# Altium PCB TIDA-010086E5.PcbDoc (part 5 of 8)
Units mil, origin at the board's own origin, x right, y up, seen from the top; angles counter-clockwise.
Board outline 6400 x 6200 mil, 6 copper layers (Top Layer, Power, AGND, Signal, PGND, Bottom Layer), stack 70.536 mil thick; 717 components, 376 nets, 2259 pads, 2183 vias.
Unrouted connection lines stored in the file: 1424.
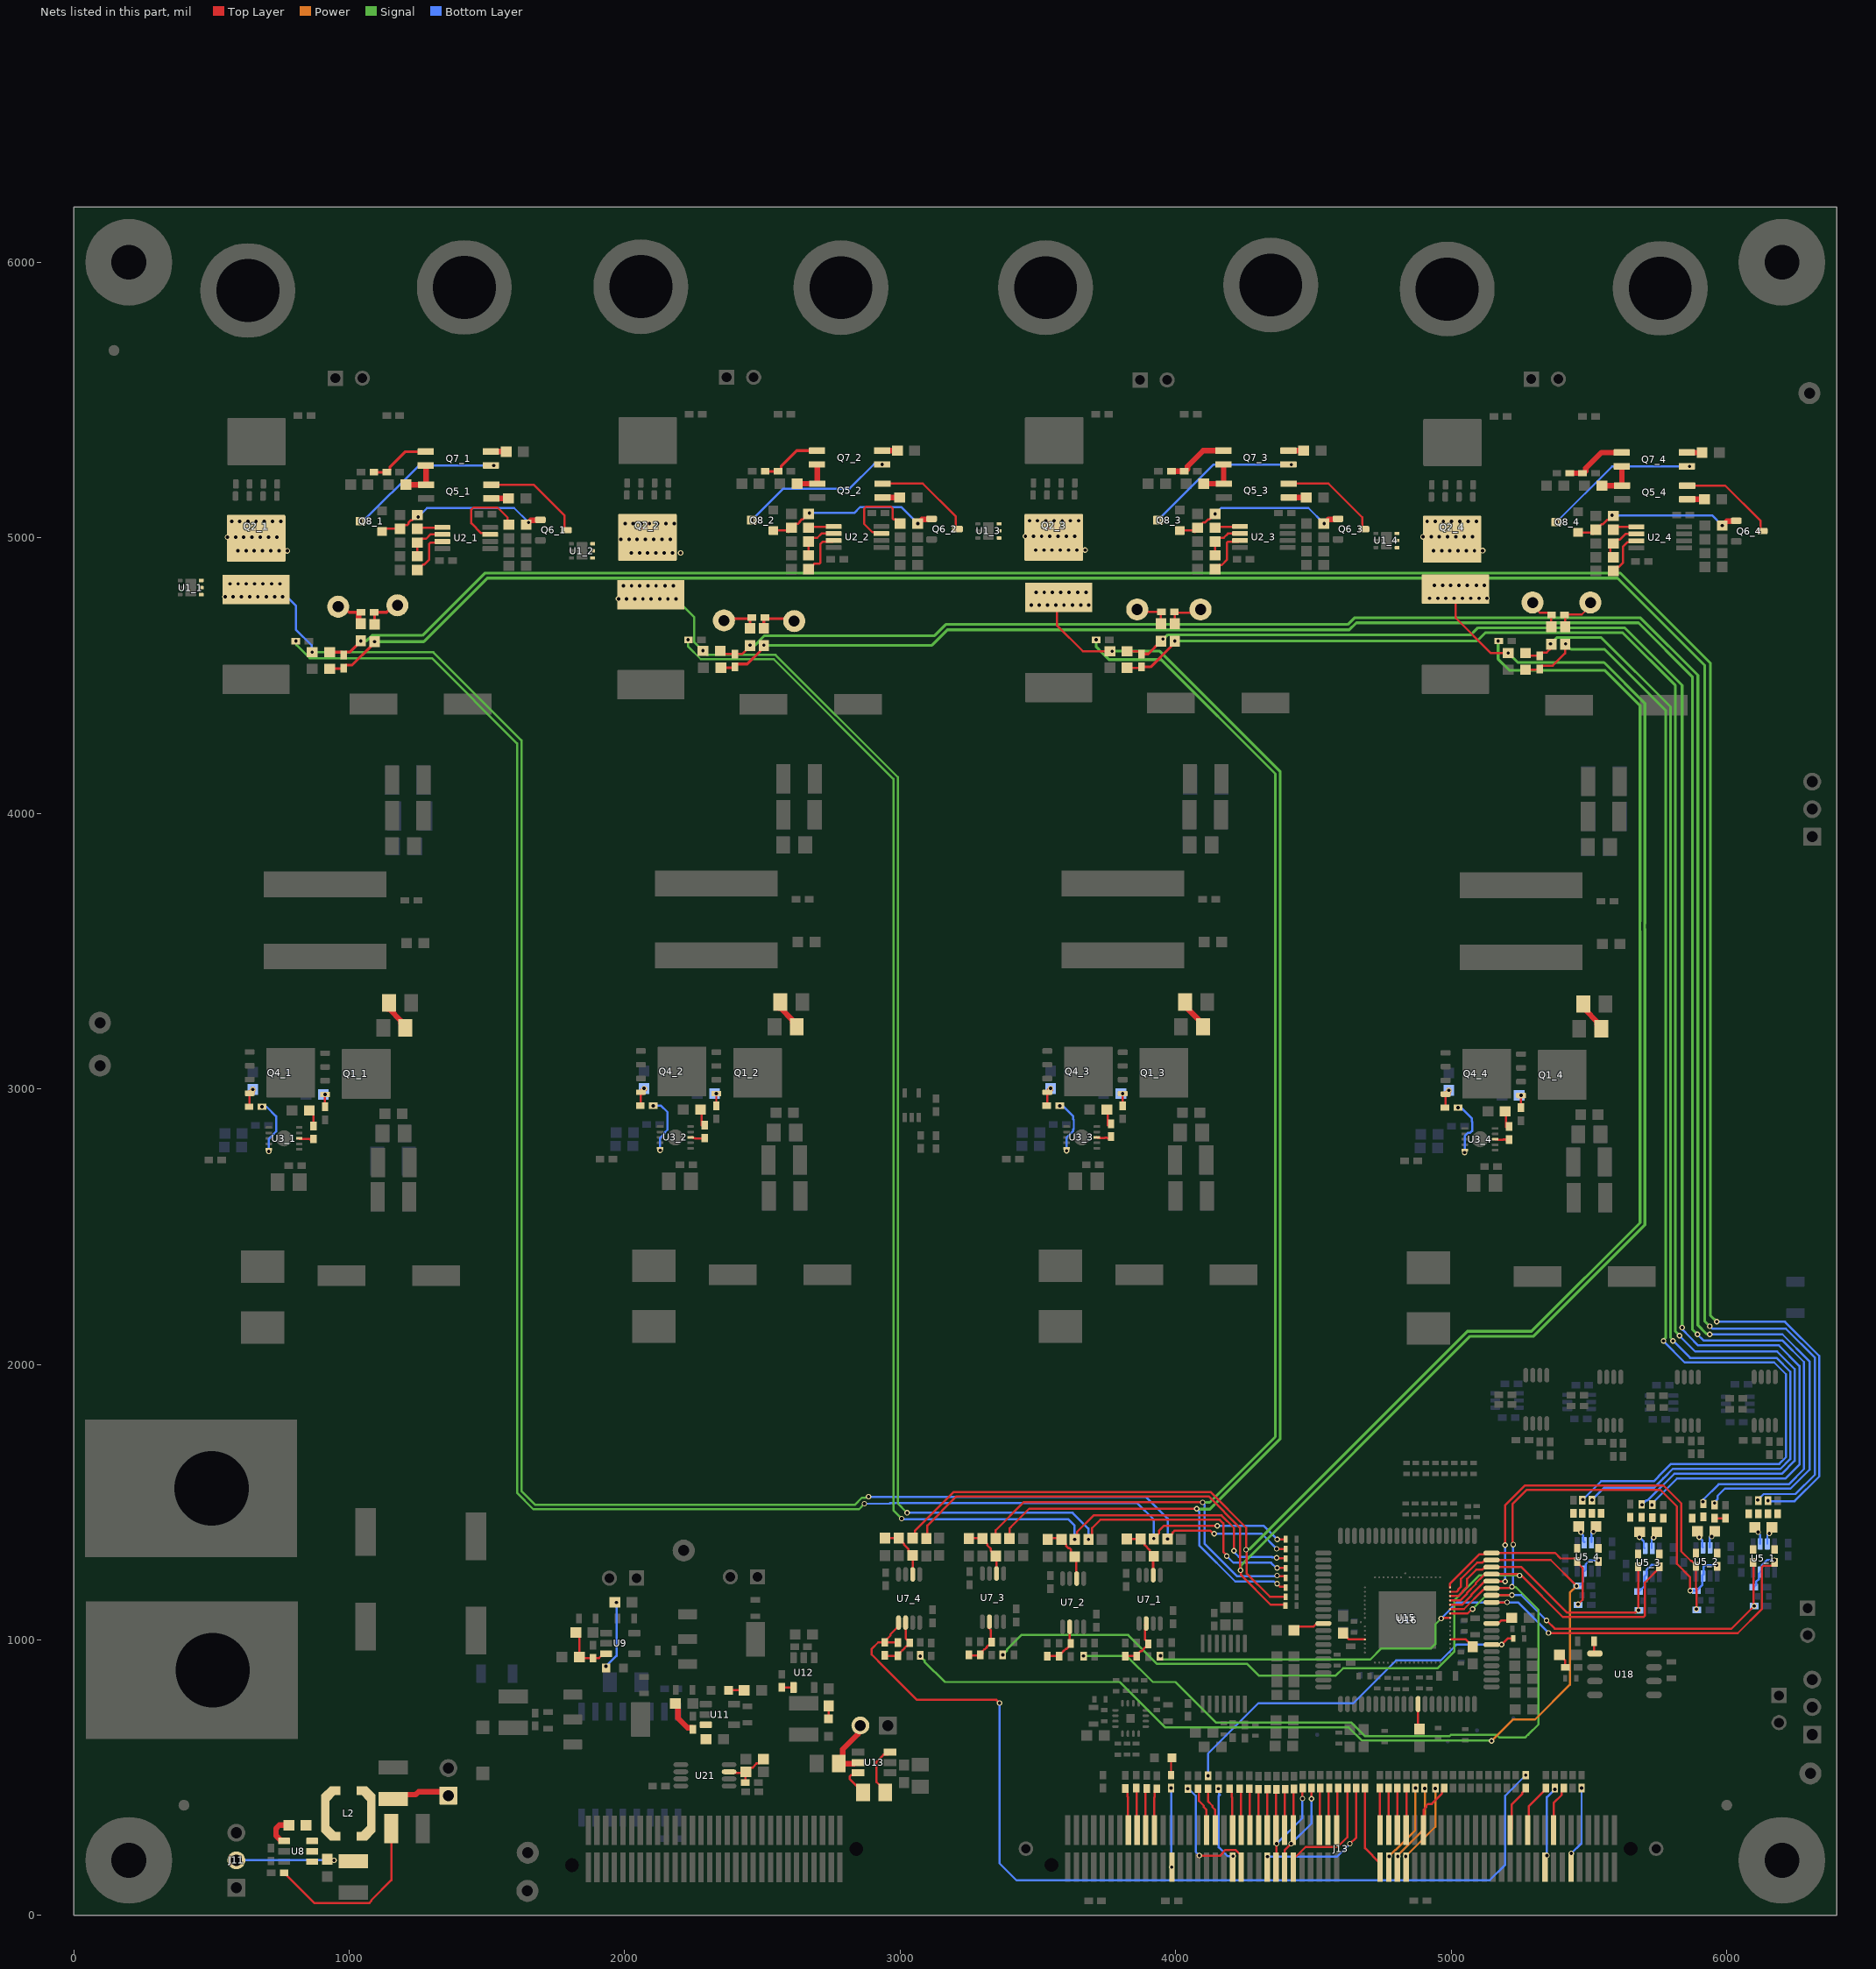
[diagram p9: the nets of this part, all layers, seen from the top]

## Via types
v1: diameter 20, hole 12.5, Top Layer to Bottom Layer, 1408 vias
v2: diameter 20, hole 12, Top Layer to Bottom Layer, tented both sides, 775 vias

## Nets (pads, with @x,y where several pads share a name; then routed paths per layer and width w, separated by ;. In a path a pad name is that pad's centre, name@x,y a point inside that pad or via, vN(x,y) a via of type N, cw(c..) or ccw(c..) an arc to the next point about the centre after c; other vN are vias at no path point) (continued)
IOCP4: C35_4.1 R51_4.1 R128.2 U7_4.1 | length 3579.4
  Top Layer w7.87: C35_4.1@2991.87,990 2991.59,990.28 2944.09,990.28 R51_4.1@2943.3,991.08 ; U7_4.1@2993.8,1062.71 2993.8,1047.09 2990.24,1043.52 2987.83,1043.52 2964.36,1020.05 2964.36,1016.08 2943.3,995.02 R51_4.1@2943.3,991.08 ; v2(3360.22,770.9) 3348.89,782.22 3060.64,782.22 2941.69,901.18 2896.33,946.54 2896.33,967.36 2920.05,991.08 R51_4.1@2943.3,991.08 ; R128.2@5270.07,509.13 v2(5270.3,509.13)
  Bottom Layer w7.87: v2(3360.22,770.9) 3360.22,189.51 3422.09,127.63 5139.36,127.63 5195.73,184.01 5195.73,434.56 v2(5270.3,509.13)
IoutN1: R40_1.2 R41_1.2 U15.58 U16.74 | length 1447.1
  Top Layer w7.87: U15.58@4995.57,1095.97 5059.06,1095.97 5074.92,1111.83 v2(5077.45,1111.83) ; U16.74@5146.16,1161.92 5146.5,1162.26 5219.52,1162.26 v2(5219.86,1162.6) ; v2(5345.75,1070.57) 5375.76,1040.56 5540.05,1040.56 5540.38,1040.23 6016.3,1040.23 v2(6099.19,1123.12) 6097.62,1124.7 6097.62,1279.31 R41_1.2@6096.04,1280.88
  Signal w7.87: v2(5077.45,1111.83) 5128.23,1162.6 v2(5219.86,1162.6)
  Bottom Layer w7.87: v2@5222.39,1163.33 5223.11,1162.6 5253.72,1162.6 v2(5345.75,1070.57)
IoutN2: R40_2.2 R41_2.2 U15.60 U16.76 | length 1618.9
  Top Layer w7.87: U15.60@4995.57,1127.47 5036.22,1127.47 5038.73,1127.47 5073.33,1162.06 5073.33,1164.58 5116.93,1208.18 5117.91,1208.18 5122.83,1213.1 U16.76@5146.16,1213.1 5146.65,1212.61 5195.32,1212.61 v2(5195.81,1212.12) ; v2(5195.81,1343.78) 5195.81,1489.03 5267.53,1560.75 5769.47,1560.75 5834.9,1495.32 5834.9,1321.5 5869.65,1286.76 5872.27,1286.76 5889.74,1269.28 R41_2.2@5889.74,1267.07 ; R41_2.2@5888.02,1267.07 5888.02,1188.5 5889.74,1186.77 v2(5889.74,1111.83)
  Bottom Layer w7.87: v2(5195.81,1212.12) v2(5195.81,1343.78)
IoutN3: R40_3.2 R41_3.2 U15.62 U16.78 | length 952.6
  Top Layer w7.87: U15.62@4995.57,1158.97 5025.69,1158.97 5041.83,1175.11 5041.83,1177.62 5057.58,1193.37 5057.58,1221.53 5090.48,1254.44 5112.01,1254.44 5116.93,1259.36 5117.91,1259.36 5122.83,1264.28 U16.78@5146.16,1264.28 ; U16.78@5169.07,1264.96 5169.75,1264.28 5255.08,1264.28 5420.6,1098.76 5668.66,1098.76 5677.57,1107.66 v2(5679.34,1107.66) 5678.72,1108.28 5678.72,1264.16 R41_3.2@5678.1,1264.78
IoutN4: R40_4.2 R41_4.2 U15.64 U16.80 | length 707
  Top Layer w7.87: U15.64@4995.57,1190.46 4995.57,1204.9 5101.85,1311.18 5118.55,1311.18 5122.83,1315.46 5377.21,1315.46 5397.15,1295.53 5450.2,1295.53 5457.01,1288.72 5457.01,1280.84 5476.85,1261 5476.85,1145.99 v2(5460.35,1129.49)
IoutP1: R33_1.2 R36_1.2 R46_1.1 U5_1.7 U15.57 U16.73 | length 2858.4
  Top Layer w7.87: R46_1.1@3942.54,941.29 3943.63,941.29 v2(3944.68,942.34) ; v2(4963.44,1077.79) 4965.77,1080.11 4974.17,1080.11 4974.28,1080.23 U15.57@4995.98,1080.23 ; U16.73@5146.16,1136.33 v2(5202.9,1136.33) ; v2(5353.14,1025.09) 5353.42,1024.81 5533.53,1024.81 5533.85,1024.48 6039.77,1024.48 6126.95,1111.66 6126.95,1263.38 6132.64,1269.07 6164.94,1269.07 6172.82,1276.94 v2(6172.82,1289.52)
  Signal w7.87: v2(3944.68,942.34) 3947,940.02 3947,932.04 3948.74,930.29 3948.74,928.49 4705.68,928.49 4746.68,969.5 4926.51,969.5 4941.9,984.88 4941.9,1056.24 v2(4963.44,1077.79)
  Bottom Layer w7.87: v2(4963.44,1077.79) 5021.98,1136.33 5241.9,1136.33 v2(5353.14,1025.09) ; R36_1.2@6098.01,1191.75 6098.25,1191.75 6106.13,1199.62 6106.13,1210.76 6116.71,1221.34 6116.71,1240.84 6126.56,1250.68 6126.56,1270.18 6147.07,1290.69 6171.64,1290.69 v2(6172.82,1289.52)
IoutP2: R33_2.2 R36_2.2 R46_2.1 U5_2.7 U15.59 U16.75 | length 4047.8
  Top Layer w7.87: U15.59@4995.57,1111.72 5046.06,1111.72 5116.93,1182.59 5117.91,1182.59 5122.83,1187.51 5210.88,1187.51 5216.62,1193.25 v2(5219.86,1193.25) ; v2(5225,1346.08) 5222.81,1348.28 5222.81,1493.76 5274.05,1545 5758.26,1545 5819.16,1484.1 5819.16,1275.56 5867.02,1227.7 v2(5867.02,1178.65)
  Signal w7.87: v2(3664.6,941.38) v2(3664.6,941.38) 3822.8,941.42 3917.08,847.14 3999.3,847.14 4145.69,700.75 4636.22,700.75 4686.97,649.99 4993.49,649.99 4998.84,655.34 5165.29,655.34 5174.86,645.78 5267.6,645.78 5278.06,656.23 5279.33,656.23 5316.81,693.71 5316.81,1108.57 5233.55,1191.83 5221.28,1191.83 v2(5219.86,1193.25)
  Bottom Layer w7.87: v2(5219.86,1193.25) 5222.18,1195.57 5222.18,1202.42 5223.69,1203.92 5223.69,1344.77 v2(5225,1346.08) ; v2(5867.02,1178.65) 5867.37,1178.29 5889.63,1178.29 R36_2.2@5889.98,1177.94 ; R36_2.2@5888.56,1180.45 5892.5,1180.45 5910.84,1198.8 5910.84,1233.13 5916.04,1238.32 5916.04,1266.52 5920.65,1271.14 v2(5963.36,1271.14)
IoutP3: R33_3.2 R36_3.2 R46_3.1 U5_3.7 U15.61 U16.77 | length 3395.8
  Top Layer w7.87: U15.61@4995.57,1143.22 5032.21,1143.22 5057.58,1168.59 5057.58,1171.1 5089.07,1202.59 5089.07,1205.91 5116.93,1233.77 5117.91,1233.77 5122.83,1238.69 5239.57,1238.69 5244.49,1233.77 v2(5247.77,1233.77) 5250.09,1231.45 5256.98,1231.45 5405.42,1083.01 5697.2,1083.01 5703.05,1088.87 5703.05,1209.03 5754.87,1260.85 5752.72,1262.99 v2(5752.72,1272.13)
  Signal w7.87: v2(3372.1,945.74) 3388.19,961.82 3388.19,966.07 3439.74,1017.63 3827.55,1017.63 3932.43,912.75 4259.13,912.75 4301.29,870.59 4580.76,870.59 4606.99,896.81 4950.3,896.81 5011.6,958.12 5011.6,1144.43 5101.1,1233.93 5247.62,1233.93 v2(5247.77,1233.77)
  Bottom Layer w7.87: R36_3.2@5678.16,1176.28 5682.1,1176.28 5700.44,1194.63 5700.44,1228.96 5708.61,1237.13 5708.61,1254.09 5726.66,1272.13 v2(5752.72,1272.13)
IoutP4: R33_4.2 R36_4.2 R46_4.1 U5_4.7 U15.63 U16.79 | length 3647.1
  Top Layer w7.87: U15.63@4995.57,1174.71 5019.16,1174.71 5026.08,1181.63 5026.08,1184.14 5035.35,1193.41 5035.35,1221.58 5093.8,1280.03 5112.01,1280.03 5116.93,1284.95 5117.91,1284.95 5122.83,1289.87 5360.82,1289.87 v2(5455.04,1195.65)
  Signal w7.87: v2(3072.4,941.22) 3088.3,925.32 3088.3,920.71 3161.86,847.14 3797.39,847.14 3962.33,682.2 4353.94,682.2 4354.6,682.87 4372.67,682.87 4373.34,682.2 4627.88,682.2 4675.83,634.25 5145.69,634.25 v2(5146.41,633.53)
  Power w7.87: v2(5146.41,633.53) 5223.39,710.51 5303.69,710.51 5430.58,837.4 5430.58,1171.19 v2(5455.04,1195.65)
  Bottom Layer w7.87: R36_4.2@5462.92,1195.65 5478.66,1211.39 5478.66,1245.73 U5_4.7@5482.6,1249.66 5487.52,1254.58 5487.52,1274.08 5502.23,1288.79 v2(5533.97,1288.79)
ISENA1: C107_1.1 R4_1.1 R12_1.2 R37_1.1 | length 8772.2
  Top Layer w7.87: v2(6112.63,1508.13) 6112.63,1507 R37_1.1@6114.41,1505.22
  Top Layer w10: R4_1.1@928.54,4524.68 977.72,4524.68 C107_1.1@980.47,4527.44 980.47,4531.38 987.28,4538.19 1010.82,4538.19 1078.14,4605.51 1078.14,4609.27 v2(1091.84,4622.97)
  Signal w10: v2(1091.84,4622.97) 1270.63,4622.97 1501.4,4853.75 5603.53,4853.75 5920,4537.28 5920,2156.21 v2(5937.77,2138.44)
  Bottom Layer w7.87: v2(5937.77,2138.44) 5938.95,2138.44 5948.45,2128.94 6214.95,2128.94 6320,2023.9 6320,1600 6249.33,1529.33 6133.83,1529.33 v2(6112.63,1508.13)
ISENA2: C107_2.1 R4_2.1 R12_2.2 R37_2.1 | length 7313.3
  Top Layer w10: R4_2.1@2348.66,4528.27 2397.83,4528.27 C107_2.1@2400.59,4531.02 2400.59,4534.96 2407.4,4541.77 2444.86,4541.77 2491.3,4588.21 2491.3,4596.3 v2(2505,4610)
  Signal w10: v2(2505,4610) 3115,4610 3170.9,4665.9 4629.84,4665.9 4655.44,4691.5 5679.75,4691.5 5875,4496.25 5875,2127.38 v2(5893.29,2109.08)
  Bottom Layer w7.87: v2(5893.29,2109.08) 5915.1,2087.27 6201.51,2087.27 6280,2008.79 6280,1620 6224.88,1564.88 5970.27,1564.88 5915.86,1510.47 5915.86,1503.61 v2(5913.54,1501.29)
ISENA3: C107_3.1 R4_3.1 R12_3.2 R37_3.1 | length 5912.2
  Top Layer w7.87: R4_3.1@3823.66,4528.27 3872.83,4528.27 C107_3.1@3875.59,4531.02
  Top Layer w10: C107_3.1@3875.59,4531.02 3908.65,4531.02 3982.48,4604.86 3982.48,4611.45 v2(3996.18,4625.15)
  Signal w10: v2(3996.18,4625.15) 5092.98,4625.15 5123.58,4655.75 5375.47,4655.75 5621.53,4655.75 5813.65,4463.64 5813.65,2119.45 v2@5828.33,2104.77
  Bottom Layer w7.87: v2(5692.41,1490.46) 5708.45,1506.5 5712.78,1506.5 5809.16,1602.87 6199.19,1602.87 6246.17,1649.86 6246.17,1983.29 6182.94,2046.52 5885.71,2046.52 v2(5828.33,2103.9)
ISENA4: C107_4.1 R4_4.1 R12_4.2 R37_4.1 | length 4555.9
  Top Layer w7.87: R4_4.1@5269.44,4521.43 5318.61,4521.43 C107_4.1@5321.37,4524.18 5321.37,4528.12 5329.24,4536 5368.19,4536 5413.01,4580.82 R12_4.2@5413.01,4613.5
  Signal w10: v2(5415,4615) 5435,4595 5557.02,4595 5777.87,4374.15 5777.87,2095.79 5770.16,2088.08 v2(5770.16,2085.37)
  Bottom Layer w7.87: v2(5477.44,1509.33) 5543.9,1575.79 5734.91,1575.79 5752.22,1593.1 5752.22,1594.14 5796.86,1638.78 6190.55,1638.78 6214.68,1662.9 6214.68,1964.23 6171.73,2007.18 5847.23,2007.18 5770.16,2084.25 v2(5770.16,2085.37)
ISENB1: C107_1.2 R5_1.1 R13_1.2 R34_1.1 | length 8761
  Top Layer w10: R5_1.1@928.54,4584.68 973.66,4584.68 C107_1.2@980.47,4577.87 ; C107_1.2@980.47,4574.68 C107_1.2@980.47,4577.87 ; v2(1041.84,4625.8) 1041.84,4624.82 1002.46,4585.43 987.28,4585.43 980.47,4578.62 C107_1.2@980.47,4577.87
  Signal w10: v2(1041.84,4625.8) 1062.32,4625.8 1082.36,4645.85 1265.85,4645.85 1491.63,4871.63 5614.4,4871.63 5940,4546.03 5940,2178.14 v2(5963.29,2154.85)
  Bottom Layer w7.87: v2(5963.29,2154.85) 6211.32,2154.85 6335.75,2030.42 6335.75,1593.48 6245.89,1503.62 6151.01,1503.62 v2(6149.41,1505.22)
ISENB2: C107_2.2 R5_2.1 R13_2.2 R34_2.1 | length 7318.1
  Top Layer w7.87: R5_2.1@2346.5,4590 2358.23,4578.27 C107_2.2@2400.59,4578.27 2425.75,4578.27 2455,4607.52 R13_2.2@2455,4608.5 v2(2455,4610) ; v2(5955.51,1496.6) 5955.6,1496.51 R34_2.1@5955.6,1488.93
  Signal w10: v2(2455,4610) 2472.65,4610 2507.46,4644.81 3124.53,4644.81 3165.14,4685.42 4624.08,4685.42 4648.04,4709.37 5687.16,4709.37 5895,4501.53 5895,2142.11 5926.11,2111 5935.86,2111 v2(5937.77,2109.08)
  Bottom Layer w7.87: v2(5937.77,2109.08) 6201.97,2109.08 6299.95,2011.11 6299.95,1617.68 6231.41,1549.14 5993.54,1549.14 5966.46,1522.06 5966.46,1510.83 5955.51,1499.88 v2(5955.51,1496.6)
ISENB3: C107_3.2 R5_3.1 R13_3.2 R34_3.1 | length 5909.6
  Top Layer w7.87: R5_3.1@3823.66,4588.27 3867.72,4588.27 3875.59,4580.39 C107_3.2@3875.59,4578.27
  Top Layer w10: C107_3.2@3875.59,4578.27 3900.28,4578.27 R13_3.2@3946.18,4624.17
  Signal w10: v2(3953.7,4632.87) 3956.41,4632.87 3971.56,4648.02 5071.64,4648.02 5097.24,4673.62 5628.94,4673.62 5837.93,4464.63 v2(5837.93,2133.85)
  Bottom Layer w7.87: v2(5728.56,1489.69) 5728.56,1491.9 5733.03,1496.37 5733.03,1499.11 5818.92,1585 6212.64,1585 6263.7,1636.06 6263.7,1993.98 6189.25,2068.42 5896.58,2068.42 5862.54,2102.46 5839.84,2125.16 5839.84,2131.94 v2(5837.93,2133.85)
ISENB4: C107_4.2 R5_4.1 R13_4.2 R34_4.1 | length 4537.8
  Top Layer w7.87: R5_4.1@5269.44,4581.43 5279.44,4571.43 C107_4.2@5321.37,4571.43 5321.37,4575.37 5329.24,4583.24 5346.31,4583.24 5363.01,4599.94 R13_4.2@5363.01,4600.93
  Signal w10: v2(5360,4615) 5382.87,4637.87 5544.64,4637.87 5795.75,4386.77 5795.75,2096.81 5804.87,2087.69 v2(5804.87,2085.37)
  Bottom Layer w7.87: v2(5510.83,1508.13) 5555.25,1552.55 5736.57,1552.55 5770.1,1586.08 5770.1,1586.73 5804.11,1620.75 6194.79,1620.75 6230.43,1656.38 6230.43,1973.76 6180.67,2023.51 5866.73,2023.51 v2(5804.87,2085.37)
LED_BLINK: J13.96 R125.2 | length 287.5
  Bottom Layer w7.87: v2(3983,461.88) 3984.34,460.54 3984.34,176.85 v2(3985.69,175.5)
LO_1: R10_1.1 U3_1.10 | length 211.7
  Top Layer w7.87: v2(708.31,2772.99) U3_1.10@708.31,2780.87
  Bottom Layer w7.87: v2(683.62,2935.04) 699.96,2935.04 734.8,2900.2 734.8,2845.1 723.3,2833.59 ; v2(708.31,2772.99) 708.31,2818.58 723.3,2833.57
LO_2: R10_2.1 U3_2.10 | length 218.1
  Top Layer w7.87: v2(2128.43,2776.87) U3_2.10@2128.43,2784.45
  Bottom Layer w7.87: v2(2103.74,2938.62) 2132.01,2938.62 2154.92,2915.71 2154.92,2851.56 2143.43,2840.07 2143.43,2837.16 2128.43,2822.16 v2(2128.43,2776.87)
LO_3: R10_3.1 U3_3.10 | length 211.3
  Top Layer w7.87: v2(3603.43,2775.1) U3_3.10@3603.43,2784.45
  Bottom Layer w7.87: v2(3578.74,2938.62) 3580.94,2936.42 3591.64,2936.42 3628.11,2899.95 3628.11,2889.58 3629.92,2887.77 3629.92,2854.36 3628.11,2852.55 3628.11,2847.51 3603.43,2822.83 v2(3603.43,2775.1)
LO_4: R10_4.1 U3_4.10 | length 215.6
  Top Layer w7.87: v2(5048.67,2768.57) 5048.94,2768.83 5048.94,2777.34 U3_4.10@5049.2,2777.61
  Bottom Layer w7.87: v2(5024.52,2931.78) 5026.64,2929.66 5037.49,2929.66 5073.89,2893.27 5073.89,2882.74 5075.7,2880.93 5075.7,2847.52 5068.78,2840.6 5061.3,2840.6 5048.67,2827.97 v2(5048.67,2768.57)
LOCSEN_N1: R11_1.2 R50_1.2 R88.1 | length 6645.6
  Top Layer w7.87: v2(3920.3,1367.6) 3939.78,1387.09 3939.78,1396.85 3957.13,1414.2 v2(4150.71,1414.2) ; v2(4368.21,1365.05) 4368.41,1365.25 4398.19,1365.25 R88.1@4398.38,1365.45
  Signal w7.87: v2(806.38,4625) 808.67,4622.7 808.67,4610.72 856.52,4562.87 1299.94,4562.87 1609,4253.81 1609,1533.73 1668.48,1474.25 2849.96,1474.25 v2(2870,1494.29)
  Bottom Layer w7.87: v2(2870,1494.29) 2961.87,1494.29 2963.58,1496 3860.79,1496 3920.3,1436.5 v2(3920.3,1367.6) ; v2(4150.71,1414.2) 4319.06,1414.2 v2(4368.21,1365.05)
LOCSEN_N2: R11_2.2 R50_2.2 R94.1 | length 5281.9
  Top Layer w7.87: v2(3632.95,1365.07) 3632.95,1366.05 3642.04,1375.14 3642.04,1391.95 3701.84,1451.76 4166.27,1451.76 4211.15,1406.87 v2(4211.15,1323.45) ; v2(4366.42,1297.97) 4367.68,1296.71 4397.12,1296.71 R94.1@4398.38,1295.45
  Signal w7.87: v2(2230,4630) 2230,4605 2275.75,4559.25 2540.75,4559.25 2975,4125 2975,1470 v2(3005,1440)
  Bottom Layer w7.87: v2(3005,1440) 3006.56,1438.44 3608.71,1438.44 3632.95,1414.2 v2(3632.95,1365.07) ; v2(4211.15,1323.45) 4211.15,1320.16 4216.54,1314.78 4216.54,1313.73 4229.31,1300.96 4349.43,1300.96 4350.12,1300.27 4364.13,1300.27 v2(4366.42,1297.97)
LOCSEN_N3: R11_3.2 R50_3.2 R96.1 | length 4959.9
  Top Layer w7.87: R50_3.2@3346.51,1368.82 3346.51,1398.03 3447.67,1499.19 v2(4097.68,1499.19) ; v2(4367.68,1233.44) 4369.98,1231.14 4395.88,1231.14 4398.38,1228.64 R96.1@4398.38,1225.45
  Signal w10: v2(3711.08,4630) 3711.39,4629.68 3711.39,4604 3731.16,4584.23 3757.73,4557.67 3947.33,4557.67 4361.38,4143.62 4361.38,1737.41 4123.16,1499.19 v2(4097.68,1499.19)
  Bottom Layer w7.87: v2(4097.68,1499.19) 4097.68,1496.49 4105,1489.16 4105,1348.3 4222.51,1230.79 4357.01,1230.79 4357.33,1231.12 4365.36,1231.12 v2(4367.68,1233.44)
LOCSEN_N4: R11_4.2 R50_4.2 R99.1 | length 6138.8
  Top Layer w7.87: R50_4.2@3044.99,1369.64 3053.15,1377.81 3053.15,1395.96 3193.94,1536.75 4125.81,1536.75 4255,1407.56 v2(4255,1327.18) 4256.8,1325.38 4256.8,1241.5 4341.51,1156.78 R99.1@4398.38,1156.78 ; v2(5170,4625) 5170.3,4625.3 R11_4.2@5171.99,4625.3
  Signal w10: v2(4255,1327.18) 4257.22,1329.39 4267.88,1329.39 5058.55,2120.06 5291.3,2120.06 5685.08,2513.84 5685.08,3572.29 5684.25,3573.12 5684.25,3606.88 5685.08,3607.71 5685.08,4391.31 5557.02,4519.37 5210.56,4519.37 5170,4559.93 v2(5170,4625)
LOCSEN_P1: Q2_1.5 Q2_1.6 Q2_1.7 Q2_1.8 Q2_1.9@662.13,4998.15 R1_1.2 R5_1.2 R47_1.2 R87.1 U1_1.4 U1_1.5 U1_1.6 | length 6826.8
  Top Layer w7.87: v2(3970.3,1366.62) 3970.3,1367.6 3988.37,1385.67 3988.37,1388.9 3995.29,1395.82 4125.47,1395.82 4135.96,1385.32 v2(4139.24,1385.32) ; v2(4366.42,1330.45) R87.1@4398.38,1330.45
  Signal w7.87: v2(865.55,4584.68) 1305.32,4584.68 1625,4265 1625,1540 1675,1490 2834.87,1490 2860.97,1516.1 2874.32,1516.1 2875.35,1517.12 2882.68,1517.12 v2(2885,1519.44)
  Bottom Layer w7.87: v1(757.92,4786.14) 760.62,4783.44 776.76,4783.44 806.38,4753.82 806.38,4667.1 863.26,4610.23 863.26,4586.98 v2(865.55,4584.68) ; v2(2885,1519.44) 3891.31,1519.44 3970.3,1440.46 v2(3970.3,1366.62) ; v2(4139.24,1385.32) 4311.55,1385.32 v2(4366.42,1330.45)
  other v1: 549.32,4786.14 579,4786.14 608.13,4786.14 638.13,4786.14 668.13,4786.14 699.1,4786.14 728.79,4786.14 567.07,4832.85 596.76,4832.85 625.89,4832.85 655.89,4832.85 685.89,4832.85 718.98,4832.85 748.66,4832.85 596.08,4952.54 625.77,4952.54 654.9,4952.54 684.9,4952.54 714.9,4952.54 744.9,4952.54 774.9,4952.54 558.31,5002.47 587.99,5002.47 617.13,5002.47 647.13,5002.47 677.13,5002.47 707.13,5002.47 737.13,5002.47 573.07,5059.09 602.76,5059.09 631.89,5059.09 661.89,5059.09 691.89,5059.09 721.89,5059.09 751.89,5059.09
LOCSEN_P2: Q2_2.5 Q2_2.6 Q2_2.7 Q2_2.8 Q2_2.9@2082.24,5001.73 R1_2.2 R5_2.2 R47_2.2 R89.1 U1_2.4 U1_2.5 U1_2.6 | length 5427.4
  Top Layer w7.87: v2(3682.95,1365.07) 3682.95,1366.05 3695.83,1378.94 3695.83,1405.81 3726.03,1436.01 4159.74,1436.01 4172.52,1423.23 4172.52,1319.92 4185,1307.45 v2(4185,1304.2) ; v2(4367.68,1261.49) 4368.21,1260.97 4397.86,1260.97 R89.1@4398.38,1260.45
  Signal w7.87: v1(2185.79,4778.6) 2251.81,4712.59 2251.81,4621.69 v2(2283.5,4590) 2298.5,4575 2547.27,4575 2990.75,4131.52 2990.75,1495.56 v2(3025,1461.31)
  Bottom Layer w7.87: v2(3025,1461.31) 3625.44,1461.31 3682.95,1403.8 v2(3682.95,1365.07) ; v2(4185,1304.2) 4185.29,1304.2 4209.49,1280 4345.9,1280 4364.4,1261.49 v2(4367.68,1261.49)
  other v1: 1977.19,4778.6 2006.87,4778.6 2036.01,4778.6 2066.01,4778.6 2096.01,4778.6 2126.97,4778.6 2156.66,4778.6 1994.95,4825.31 2024.63,4825.31 2053.76,4825.31 2083.76,4825.31 2113.76,4825.31 2146.85,4825.31 2176.54,4825.31 2023.96,4945 2053.64,4945 2082.77,4945 2112.77,4945 2142.77,4945 2172.77,4945 2202.77,4945 1986.18,4994.93 2015.87,4994.93 2045,4994.93 2075,4994.93 2105,4994.93 2135,4994.93 2165,4994.93 2000.94,5051.55 2030.63,5051.55 2059.76,5051.55 2089.76,5051.55 2119.76,5051.55 2149.76,5051.55 2179.76,5051.55
LOCSEN_P3: Q2_3.5 Q2_3.6 Q2_3.7 Q2_3.8 Q2_3.9@3557.24,5001.73 R1_3.2 R5_3.2 R47_3.2 R95.1 U1_3.4 U1_3.5 U1_3.6 | length 5260.5
  Top Layer w7.87: R47_3.2@3396.51,1367.83 3396.51,1404.64 3401.13,1409.25 3467.88,1476 v2(4076,1476) ; R1_3.2@3569.36,4816.05 3569.36,4681.29 3662.39,4588.27 R5_3.2@3760.67,4588.27 ; v2(4367.68,1204.15) 4378.87,1192.96 4395.87,1192.96 R95.1@4398.38,1190.45
  Top Layer w10: R1_3.2@3592.43,4755.24 R1_3.2@3592.43,4770.03
  Signal w10: v2(3769.16,4588.27) 3942.01,4588.27 4379.26,4151.02 4379.26,1730.01 4123.67,1474.42 4077.58,1474.42 v2(4076,1476)
  Bottom Layer w7.87: v2(4076,1476) 4076,1474.14 4085,1465.14 4085,1343.02 4215.9,1212.12 4356.47,1212.12 4364.44,1204.15 v2(4367.68,1204.15)
  other v1: 3475.25,4755.24 3504.94,4755.24 3534.07,4755.24 3564.07,4755.24 3594.07,4755.24 3625.04,4755.24 3654.72,4755.24 3683.86,4755.24 3493.01,4801.95 3522.69,4801.95 3551.83,4801.95 3581.83,4801.95 3611.83,4801.95 3644.92,4801.95 3674.6,4801.95 3491.92,4955.41 3521.6,4955.41 3550.74,4955.41 3580.74,4955.41 3610.74,4955.41 3640.74,4955.41 3670.74,4955.41 3454.14,5005.34 3483.83,5005.34 3512.96,5005.34 3542.96,5005.34 3572.96,5005.34 3602.96,5005.34 3632.96,5005.34 3468.91,5061.96 3498.59,5061.96 3527.73,5061.96 3557.73,5061.96 3587.73,5061.96 3617.73,5061.96 3647.73,5061.96
LOCSEN_P4: Q2_4.5 Q2_4.6 Q2_4.7 Q2_4.8 Q2_4.9@5003.02,4994.89 R1_4.2 R5_4.2 R47_4.2 R97.1 U1_4.4 U1_4.5 U1_4.6 | length 6479.5
  Top Layer w7.87: R47_4.2@3094.57,1367.83 3098.47,1371.73 3098.47,1415.34 3204.13,1521 4119.29,1521 4233.19,1407.1 4233.19,1254.4 4237.31,1250.28 4237.31,1235.06 4344.51,1127.85 4395.88,1127.85 4398.38,1125.35 R97.1@4398.38,1125.05 ; R1_4.2@5015.14,4813.39 5015.14,4710.55 5144.26,4581.43 v2(5206.45,4581.43)
  Top Layer w10: R1_4.2@5038.23,4780.4 R1_4.2@5038.23,4795.18
  Signal w10: v2(4234.99,1252.6) 4234.99,1268.4 5068.77,2102.18 5298.71,2102.18 5702.96,2506.43 5702.96,3579.69 5702.13,3580.53 5702.13,3599.47 5702.96,3600.31 5702.96,4398.71 5554.39,4547.28 5241.03,4547.28 5206.88,4581.43 v2(5206.45,4581.43)
  other v1: 4921.05,4780.4 4950.74,4780.4 4979.87,4780.4 5009.87,4780.4 5039.87,4780.4 5070.84,4780.4 5100.52,4780.4 5129.66,4780.4 4938.81,4827.11 4968.49,4827.11 4997.63,4827.11 5027.63,4827.11 5057.63,4827.11 5090.72,4827.11 5120.4,4827.11 4935.35,4953.33 4965.04,4953.33 4994.17,4953.33 5024.17,4953.33 5054.17,4953.33 5084.17,4953.33 5114.17,4953.33 4897.58,5003.26 4927.26,5003.26 4956.4,5003.26 4986.4,5003.26 5016.4,5003.26 5046.4,5003.26 5076.4,5003.26 4912.34,5059.88 4942.03,5059.88 4971.16,5059.88 5001.16,5059.88 5031.16,5059.88 5061.16,5059.88 5091.16,5059.88
MCU_INT: R74.2 R158.1 U16.67 | length 1397.5
  Top Layer w7.87: U16.67@5146.16,982.79 v2(5182.54,982.79) 5204.75,1005 R74.2@5225,1005
  Bottom Layer w7.87: v2(4117.05,507) 4117.05,587.08 4299.86,769.88 4643.86,769.88 4799.86,925.88 4962.33,925.88 5019.02,982.57 5116.63,982.57 5116.85,982.79 v2(5182.54,982.79)
NetC19_1_1: C19_1.1 R3_1.1 | length 160.9
  Top Layer w20: C19_1.1@1144.52,3311.42 1130.82,3297.72 1138.62,3289.92 1145.12,3289.92 R3_1.1@1188.62,3246.42 ; R3_1.1@1188.62,3246.42 1203.62,3231.42 R3_1.1@1203.62,3221.42 1188.62,3236.42 R3_1.1@1188.62,3246.42
NetC19_2_1: C19_2.1 R3_2.1 | length 160.9
  Top Layer w20: C19_2.1@2564.64,3315 2550.94,3301.3 2558.74,3293.5 2565.24,3293.5 R3_2.1@2608.74,3250 ; R3_2.1@2608.74,3250 2623.74,3235 R3_2.1@2623.74,3225 2608.74,3240 R3_2.1@2608.74,3250
NetC19_3_1: C19_3.1 R3_3.1 | length 148.1
  Top Layer w20: C19_3.1@4033.74,3315 4033.74,3300 4040.24,3293.5 R3_3.1@4083.74,3250 ; R3_3.1@4083.74,3250 4098.74,3235 R3_3.1@4098.74,3225 4083.74,3240 R3_3.1@4083.74,3250
NetC19_4_1: C19_4.1 R3_4.1 | length 148.1
  Top Layer w20: C19_4.1@5479.52,3308.16 5479.52,3293.16 5486.02,3286.66 R3_4.1@5529.52,3243.16 ; R3_4.1@5529.52,3243.16 5544.52,3228.16 R3_4.1@5544.52,3218.16 5529.52,3233.16 R3_4.1@5529.52,3243.16
NetC20_1_1: C20_1.1 R12_1.1 TP1_1.1 | length 128.2
  Top Layer w10: R12_1.1@1091.84,4685.97 1091.84,4728.09 C20_1.1@1090.46,4729.47 1136.03,4729.47 1156.56,4750 TP1_1.1@1166.05,4750
NetC20_1_2: C20_1.2 R13_1.1 TP2_1.1 | length 138.4
  Top Layer w10: TP2_1.1@960,4750 978.94,4750 999.47,4729.47 1034.17,4729.47 C20_1.2@1043.22,4729.47
  Top Layer w20: C20_1.2@1034.17,4729.47 1034.17,4693.63 R13_1.1@1041.84,4685.97
NetC20_2_1: C20_2.1 R12_2.1 TP1_2.1 | length 156.6
  Top Layer w10: R12_2.1@2505,4671.5 2505,4706.38 C20_2.1@2508.62,4710 2512.28,4706.34 2618.48,4706.34 TP1_2.1@2622.14,4702.68
NetC20_2_2: C20_2.2 R13_2.1 TP2_2.1 | length 141.3
  Top Layer w10: TP2_2.1@2360,4700 2366.18,4706.18 C20_2.2@2457.56,4706.18 ; R13_2.1@2455,4671.5 2455,4703.62 C20_2.2@2457.56,4706.18 ; C20_2.2@2461.38,4710 C20_2.2@2457.56,4706.18
NetC20_3_1: C20_3.1 R12_3.1 TP1_3.1 | length 134.5
  Top Layer w7.87: C20_3.1@3994.81,4731.65 3994.81,4729.16 C20_3.1@3996.18,4727.78 ; R12_3.1@3996.18,4688.14 C20_3.1@3996.18,4727.78 ; TP1_3.1@4085,4731.65 4081.14,4727.78 C20_3.1@3996.18,4727.78
NetC20_3_2: C20_3.2 R13_3.1 TP2_3.1 | length 131.6
  Top Layer w7.87: TP2_3.1@3860,4731.65 C20_3.2@3947.56,4731.65 3946.18,4730.27 R13_3.1@3946.18,4688.14
NetC20_4_1: C20_4.1 R12_4.1 TP1_4.1 | length 157.8
  Top Layer w7.87: R12_4.1@5413.01,4676.5 5413.01,4718.25 C20_4.1@5411.26,4720 5412.72,4721.46 5473.79,4721.46 5497.33,4745 TP1_4.1@5514.46,4745
NetC20_4_2: C20_4.2 R13_4.1 TP2_4.1 | length 133.3
  Top Layer w7.87: TP2_4.1@5285,4745 5304.52,4745 5321.64,4727.87 5356.15,4727.87 C20_4.2@5364.02,4720 5363.01,4718.99 R13_4.1@5363.01,4676.5
NetC24_1_1: C24_1.1 R17_1.1 | length 64.9
  Top Layer w7.87: C24_1.1@855.12,2921.42 870,2906.54 R17_1.1@870,2862.66
NetC24_2_1: C24_2.1 R17_2.1 | length 59.3
  Top Layer w7.87: C24_2.1@2275.24,2925 2278.62,2921.61 R17_2.1@2278.62,2867.13
NetC24_3_1: C24_3.1 R17_3.1 | length 59.3
  Top Layer w7.87: C24_3.1@3750.24,2925 3753.62,2921.61 R17_3.1@3753.62,2867.13
NetC24_4_1: C24_4.1 R17_4.1 | length 59.3
  Top Layer w7.87: C24_4.1@5196.02,2918.16 5199.4,2914.78 R17_4.1@5199.4,2860.29
NetC28_1_2: C28_1.2 C31_1.1 R33_1.1 R34_1.2 U5_1.3 | length 36.2
  Bottom Layer w7.87: U5_1.3@6147.22,1348.12 v2@6147.22,1384.3
  other v2: 6154.41,1386.6
NetC28_2_2: C28_2.2 C31_2.1 R33_2.1 R34_2.2 U5_2.3 | length 75.7
  Top Layer w7.87: R34_2.2@5955.6,1441.68 5955.9,1441.38 C28_2.2@5995,1441.38
  Bottom Layer w7.87: U5_2.3@5937.77,1336.83 v2@5937.77,1373.01
  other v2: 5944.95,1375.3
NetC28_3_2: C28_3.2 C31_3.1 R33_3.1 R34_3.2 U5_3.3 | length 36.2
  Bottom Layer w7.87: U5_3.3@5727.37,1332.66 v2@5727.37,1368.84
  other v2: 5734.56,1371.14
NetC28_4_2: C28_4.2 C31_4.1 R33_4.1 R34_4.2 U5_4.3 | length 36.2
  Bottom Layer w7.87: U5_4.3@5508.38,1354.49 v2@5508.38,1390.67
  other v2: 5515.56,1392.96
NetC31_1_2: C31_1.2 C32_1.2 R37_1.2 R41_1.1 U5_1.2 | length 45.7
  Bottom Layer w7.87: v2(6114.07,1390.67) 6114.07,1387.38 6120.85,1380.6 6120.85,1348.91 U5_1.2@6121.63,1348.12
NetC31_2_2: C31_2.2 C32_2.2 R37_2.2 R41_2.1 U5_2.2 | length 40.9
  Bottom Layer w7.87: v2@5899.93,1372.61 5911.24,1361.29 5911.24,1337.77 U5_2.2@5912.18,1336.83
  other v2: 5899.93,1373.01
NetC31_3_2: C31_3.2 C32_3.2 R37_3.2 R41_3.1 U5_3.2 | length 48.1
  Bottom Layer w7.87: v2(5683.02,1373.01) 5698.77,1357.26 5698.77,1335.67 U5_3.2@5701.78,1332.66
NetC31_4_2: C31_4.2 C32_4.2 R37_4.2 R41_4.1 U5_4.2 | length 41.3
  Bottom Layer w7.87: v2(5470.54,1390.67) 5470.54,1387.42 5478.93,1379.02 5478.93,1358.35 U5_4.2@5482.79,1354.49
NetC35_1_2: C35_1.2 R48_1.2 R51_1.2 U7_1.2 | length 180.8
  Top Layer w7.87: R51_1.2@3816.32,941.02 C35_1.2@3858.78,941.02 3858.78,944.96 3873.3,959.48 3876.7,959.48 3883.62,966.4 3883.62,967.36 3890.44,974.18 3892.42,974.18 3897.17,978.93 R48_1.2@3897.17,985.99 ; U7_1.2@3889.02,1053.97 3891.02,1051.96 3891.02,1038.41 3889.02,1036.4 3889.02,1001.21 3900.3,989.93 R48_1.2@3900.3,985.99
NetC35_2_2: C35_2.2 R48_2.2 R51_2.2 U7_2.2 | length 172.1
  Top Layer w7.87: R51_2.2@3533.43,940.58 3534.28,941.42 3577.18,941.42 C35_2.2@3577.24,941.37 ; C35_2.2@3577.24,940.58 3577.24,944.51 3592.98,960.26 3593.94,960.26 3600.53,966.86 3603.14,966.86 3618.88,982.6 R48_2.2@3618.88,986.54 3614.67,990.76 U7_2.2@3614.67,1047.37
NetC35_3_2: C35_3.2 R48_3.2 R51_3.2 U7_3.2 | length 190.8
  Top Layer w7.87: R51_3.2@3248.72,945.77 3251.63,942.86 3257.89,942.86 C35_3.2@3291.52,942.86 ; C35_3.2@3290.29,945.77 3290.29,944.09 C35_3.2@3291.52,942.86 ; U7_3.2@3320.53,1062.71 3320.53,1043.44 3328.69,1035.28 R48_3.2@3328.69,992.2 ; R48_3.2@3331.51,992.2 3331.51,988.27 3323.64,980.39 3319.7,980.39 3313.91,974.6 3313.91,972.38 3306.99,965.46 3304.77,965.46 3298.16,958.85 3298.16,949.51 C35_3.2@3291.52,942.86
NetC35_4_2: C35_4.2 R48_4.2 R51_4.2 U7_4.2 | length 199.6
  Top Layer w7.87: R51_4.2@2943.3,943.83 2945.07,942.06 2994.3,942.06 2999.75,947.5 2999.75,954.69 3007.5,962.44 3008.57,962.44 3015.49,969.36 3015.49,970.43 3022.55,977.49 3026.49,977.49 3034.36,985.37 3034.36,993.24 3026.49,1001.12 3024.01,1001.12 3019.39,1005.73 U7_4.2@3019.39,1062.71
NetC37_1_2: C37_1.2 R50_1.1 R52_1.1 U7_1.6 | length 200.6
  Top Layer w7.87: C37_1.2@3822.5,1366.62 R52_1.1@3872.5,1366.62 3887.26,1351.85 3887.26,1344.56 3905.53,1326.29 3905.53,1313.98 R50_1.1@3918.09,1301.42
  Top Layer w10: U7_1.6@3918.09,1234.89 R50_1.1@3918.09,1301.42
NetC37_2_2: C37_2.2 R50_2.1 R52_2.1 U7_2.6 | length 194.4
  Top Layer w7.87: C37_2.2@3537.7,1369.08 R52_2.1@3577.24,1369.08 ; R52_2.1@3585.15,1365.07 3585.15,1364.08 3602.44,1346.8 3602.44,1340.49 3609.35,1333.57 3614.63,1333.57 3619.25,1328.96 3619.25,1317.82 3630.99,1306.09 3635.49,1306.09 3638.29,1303.29 U7_2.6@3638.29,1237.91
NetC37_3_2: C37_3.2 R50_3.1 R52_3.1 U7_3.6 | length 187.2
  Top Layer w7.87: C37_3.2@3248.72,1370.06 R52_3.1@3288.26,1370.06 ; R52_3.1@3298.72,1367.83 3298.72,1366.85 3316,1349.56 3316,1343.25 3329.23,1330.03 3329.23,1323.11 3346.51,1305.82 R50_3.1@3346.51,1304.84 3349.31,1302.04 U7_3.6@3349.31,1241.1
NetC37_4_2: C37_4.2 R50_4.1 R52_4.1 U7_4.6 | length 191.7
  Top Layer w7.87: C37_4.2@2944.39,1369.08 R52_4.1@2983.93,1369.08 ; R52_4.1@2994.39,1369.08 2994.39,1368.09 3014.47,1348.01 3014.47,1345.07 3030.22,1329.32 3030.22,1321.42 R50_4.1@3044.99,1306.65 U7_4.6@3044.99,1237.91
NetC40_1: C40.1 L2.1 U8.6
NetC40_2: C40.2 U8.1 | length 115.1
  Top Layer w20: U8.1@763.34,270 753.5,270 734.14,289.35 734.14,315.76 745.86,327.48 C40.2@780.72,327.48
NetC41_1: C41.1 C42.1 J10.1 L2.2 R53.2 | length 876.9
  Top Layer w7.87: R53.2@763.62,155 767.56,155 775.43,147.13 775.43,143.19 873.11,45.51 1073.04,45.51 1079.96,52.43 1079.96,54.99 1152.91,127.94 C41.1@1152.91,315.76
  Top Layer w20: C42.1@1160,422.91 1175.59,438.5 1241.02,438.5 1251.4,448.88 1346.12,448.88 J10.1@1360,435
NetC43_1: C43.1 C44.1 J11.2 U8.4 U8.5 | length 358.6
  Top Layer w7.87: v2(945,200) v2@948.57,200
  Bottom Layer w7.87: J11.2@590,200 v2(945,200)
NetC53_2: C53.2 R59.2 R61.2 U9.3 | length 202.4
  Top Layer w7.87: R59.2@1822.32,1027.18 1835.31,1014.19 R61.2@1835.31,937.37 1849.3,937.37 1849.3,934.45 1850,933.75 C53.2@1885.32,933.75 1906.57,933.75 1922.8,949.97 U9.3@1932.64,949.97
NetC54_2: C54.2 R60.2 R62.2 U11.3 | length 130.1
  Top Layer w20: R60.2@2183.9,769.22 2184.88,769.22 2193.58,760.52 2193.58,716.08 2228.31,681.35 2245.08,681.35 2246.89,679.54 C54.2@2246.89,675.6
NetC57_1: C57.1 U13.6 | length 187.9
  Top Layer w7.87: C57.1@2945,446.5 2945,453 2913.7,484.3 2913.7,557.63 2939.62,583.54 2954.21,583.54 U13.6@2963.07,592.4
NetC57_2: C57.2 U13.3 | length 117.8
  Top Layer w7.87: U13.3@2846.93,517.6 2839.13,509.8 2822.16,509.8 2816.31,503.95 2816.31,495.19 C57.2@2865,446.5
  Top Layer w20: U13.3@2853.17,517.6 U13.3@2855.96,514.8
NetC61_1: C61.1 U12.4 | length 42.8
  Top Layer w7.87: C61.1@2570,827.8 2570.51,827.28 U12.4@2612.6,827.28
NetC63_1: C63.1 J12.2 U13.2 | length 254.1
  Top Layer w20: J12.2@2855.18,689.38 2846.58,680.77 2846.58,658.05 2791.44,602.91 2791.44,565.94 C63.1@2776.44,550.94 2832.04,550.94 U13.2@2836.1,555 ; U13.2@2836.1,555 U13.2@2846.93,555 U13.2@2836.1,555
NetC77_2: C77.2 U16.70 | length 81.6
  Top Layer w7.87: U16.70@5146.16,1059.56 5169.49,1059.56 5174.42,1064.48 5175.39,1064.48 5181.48,1070.57 C77.2@5223.23,1070.57
NetC78_1: C78.1 U15.52 | length 91.6
  Top Layer w7.87: U15.52@4997.54,1001.49 5053.06,1001.49 5077.86,976.69 C78.1@5077.86,975.7
NetC79_1: C79.1 U15.29 | length 89.5
  Top Layer w7.87: C79.1@4606.85,1023.9 4606.85,1022.92 4628.29,1001.49 U15.29@4686.52,1001.49
NetC80_1: C80.1 U16.31 | length 117.1
  Top Layer w7.87: C80.1@4429.15,1034.55 4442.85,1048.25 4500.31,1048.25 4506.69,1054.64 4507.67,1054.64 4512.59,1059.56 U16.31@4535.93,1059.56
NetC81_1: C81.1 U16.52 | length 93.4
  Top Layer w7.87: U16.52@4879.43,767.23 4879.43,680.78 C81.1@4884.35,675.86
NetC87_1: C87.1 U18.5 | length 46.1
  Top Layer w7.87: C87.1@5518.64,995.5 5518.64,953.21 U18.5@5521.35,950.5
NetC90_1: C90.1 R112.1 | length 54.5
  Top Layer w7.87: C90.1@5392.14,945.5 5393.12,945.5 5413.64,924.99 R112.1@5413.64,900.5
NetC102_1: C102.1 R156.1 R157.1 U21.3 | length 183.9
  Top Layer w7.87: U21.3@2378.7,521.18 2398.5,521.18 2402.11,517.58 2436.4,517.58 R157.1@2437.88,519.06 ; C102.1@2437.88,482.18 R157.1@2437.88,519.06 ; R156.1@2503,567.18 2502.01,567.18 2486.53,551.69 2478.42,551.69 2471.5,544.77 2471.5,543.59 2464.58,536.67 2460.37,536.67 2459.64,535.94 2454.77,535.94 R157.1@2437.88,519.06
NetD1_2: D1.2 R57.1 | length 247.6
  Bottom Layer w7.87: v2(1932.03,904.13) 1970,942.1 v2(1970,1136)
NetD2_2: D2.2 R58.1 | length 57
  Top Layer w7.87: D2.2@2376.89,817.01 R58.1@2433.9,817.01
NetD3_2: D3.2 R64.1 | length 47
  Top Layer w7.87: D3.2@2740,712.91 R64.1@2740,759.92
NetD4_2: D4.2 R125.1 | length 64
  Top Layer w7.87: R125.1@3983,509.13 3983,569.32 D4.2@3985.69,572
NetJ13_12: J13.12 R123.2 | length 302.3
  Top Layer w7.87: J13.12@5434.51,175.5 5435,176 5435,224.51 v2(5435.49,225)
  Bottom Layer w7.87: v2(5435.49,225) 5473,262.51 v2(5473,461.88)
NetJ13_15: J13.15 R124.1 | length 167.7
  Top Layer w7.87: J13.15@5371.51,309.36 5371.51,407.98 5401.26,437.73 5401.26,455.07 R124.1@5408.07,461.88
NetJ13_18: J13.18 R126.1 | length 301.5
  Top Layer w7.87: J13.18@5340.02,175.5 5339.85,175.67 5339.85,207.06 5347.11,214.32 v2(5347.11,217.27) ; v2(5376.07,457.94) R126.1@5376.07,461.88
  Bottom Layer w7.87: v2(5347.11,217.27) 5347.11,428.98 v2(5376.07,457.94)
NetJ13_21: J13.21 R127.1 | length 179.9
  Top Layer w7.87: J13.21@5277.02,309.36 5281.87,314.2 5281.87,396.74 5343.07,457.94 R127.1@5343.07,461.88
NetJ13_25: J13.25 R128.1 | length 175.7
  Top Layer w7.87: J13.25@5214.03,309.36 5218.7,314.03 5218.7,402.25 5257.69,441.24 5257.69,445.57 5270.07,457.94 R128.1@5270.07,461.88
NetJ13_45: J13.45 R129.1 | length 185.9
  Top Layer w7.87: J13.45@4899.07,309.36 4899.07,383.14 4908.91,392.98 4908.91,397.87 4915.83,404.79 4929.25,404.79 4965.69,441.24 4965.69,445.46 4966.2,445.96 4966.2,454.01 R129.1@4970.14,457.94
NetJ13_49: J13.49 R130.2 | length 153.3
  Top Layer w7.87: J13.49@4836.08,309.36 4837.04,310.32 4837.04,460.92 R130.2@4838,461.88
NetJ13_50: J13.50 R131.1 | length 331.4
  Top Layer w7.87: v2(4834.68,214) 4835.38,213.29 4835.38,176.21 J13.50@4836.08,175.5 ; v2(4942.07,461.07) R131.1@4942.07,461.88
  Power w7.87: v2(4834.68,214) 4834.68,214.3 4942.07,321.69 v2(4942.07,461.07)
NetJ13_51: J13.51 R132.2 | length 152.7
  Top Layer w7.87: R132.2@4804.07,461.88 4804.33,461.63 4804.33,309.62 J13.51@4804.58,309.36
NetJ13_52: J13.52 R133.1 | length 329
  Top Layer w7.87: J13.52@4804.58,175.5 4805.1,176.02 4805.1,213.48 v2(4805.61,214) ; R133.1@4902,461.88 4902.81,461.07 v2(4903.91,461.07)
  Power w7.87: v2(4805.61,214) 4805.61,216.7 4811.8,222.89 4811.8,223.47 4903.91,315.58 v2(4903.91,461.07)
NetJ13_53: J13.53 R134.2 | length 152.9
  Top Layer w7.87: R134.2@4772.07,461.88 4772.58,461.37 4772.58,309.87 J13.53@4773.09,309.36
NetJ13_54: J13.54 R135.1 | length 326.9
  Top Layer w7.87: J13.54@4773.09,175.5 4773.8,176.21 4773.8,213.92 v2(4774.51,214.63)
  Power w7.87: v2(4774.51,214.63) 4774.51,215.24 4796.14,236.87 4796.75,236.87 4870,310.12 v2(4870,461.88)
NetJ13_55: J13.55 R136.2 | length 153.1
  Top Layer w7.87: R136.2@4740.07,461.88 4740.83,461.12 4740.83,310.12 J13.55@4741.59,309.36
NetJ13_56: J13.56 R137.1 | length 309
  Top Layer w7.87: R137.1@4687,461.88 4687,243.87 4741.59,189.28 J13.56@4741.59,175.5
NetJ13_57: J13.57 R138.1 | length 155
  Top Layer w7.87: J13.57@4584.11,309.36 4587.06,312.31 4587.06,458.94 R138.1@4590,461.88
NetJ13_59: J13.59 R139.1 | length 154.3
  Top Layer w7.87: J13.59@4552.62,309.36 4554.81,311.55 4554.81,459.69 R139.1@4557,461.88
NetJ13_61: J13.61 R140.1 | length 154.1
  Top Layer w7.87: J13.61@4521.12,309.36 4523.06,311.3 4523.06,459.94 R140.1@4525,461.88
NetJ13_67: J13.67 R141.2 | length 150.2
  Top Layer w7.87: J13.67@4426.63,309.36 4427.82,310.55 4427.82,457.21 R141.2@4429.15,458.55
NetJ13_68: J13.68 R142.1 | length 435.8
  Top Layer w7.87: J13.68@4426.63,175.5 4431.47,180.35 4431.47,208.79 4471.24,248.55 4587.5,248.55 4623,284.06 R142.1@4623,461.88
NetJ13_69: J13.69 R144.2 | length 153.3
  Top Layer w7.87: J13.69@4395.14,309.36 4396.07,310.29 4396.07,460.95 R144.2@4397,461.88
NetJ13_70: J13.70 R145.1 | length 327.3
  Top Layer w7.87: J13.70@4395.14,175.5 4395.14,236.45 v2(4418.68,260) ; v2(4492.5,423.63) 4492.5,461.39 R145.1@4493,461.88
  Bottom Layer w7.87: v2(4418.68,260) 4493,334.32 4493,423.14 v2(4492.5,423.63)
NetJ13_71: J13.71 R146.2 | length 148.8
  Top Layer w7.87: J13.71@4363.64,309.36 4364.32,310.04 4364.32,456.95 R146.2@4365,457.63
NetJ13_72: J13.72 R147.1 | length 326.7
  Top Layer w7.87: J13.72@4363.64,175.5 4365.03,176.89 4365.03,258.61 v2(4366.42,260) ; v2(4459.88,424.19) 4459.88,460.76 R147.1@4461,461.88
  Bottom Layer w7.87: v2(4366.42,260) 4459.88,353.46 v2(4459.88,424.19)
NetJ13_73: J13.73 R148.2 | length 152.9
  Top Layer w7.87: J13.73@4332.14,309.36 4332.57,309.79 4332.57,461.45 R148.2@4333,461.88
NetJ13_74: J13.74 R149.1 | length 568.1
  Top Layer w7.87: J13.74@4332.14,175.5 4332.36,175.72 4332.36,213.08 v2(4332.57,213.29) ; v2(4631.96,260) 4655,283.04 R149.1@4655,461.88
  Bottom Layer w7.87: v2(4332.57,213.29) 4585.26,213.29 v2(4631.96,260)
NetJ13_75: J13.75 R150.2 | length 152.8
  Top Layer w7.87: R150.2@4299.66,463.76 R150.2@4299.99,463.44 ; R150.2@4300.32,461.56 4300.32,309.69 J13.75@4300.65,309.36
NetJ13_77: J13.77 R151.2 | length 151.2
  Top Layer w7.87: R151.2@4267.2,459.76 4268.58,458.38 4268.58,309.94 J13.77@4269.15,309.36
NetJ13_79: J13.79 R152.2 | length 152.6
  Top Layer w7.87: R152.2@4232.3,459.76 4236.83,455.23 4236.83,310.19 J13.79@4237.65,309.36
NetJ13_80: J13.80 R153.1 | length 472.5
  Top Layer w7.87: v2(4085.89,217.27) 4161.6,217.27 4166.85,222.52 4166.85,223.66 4180.69,237.5 4216.71,237.5 4237.65,216.56 J13.80@4237.65,175.5
  Bottom Layer w7.87: v2(4043.58,459.76) 4046.86,459.76 4072.74,433.88 4072.74,230.42 v2(4085.89,217.27)
NetJ13_81: J13.81 R154.2 | length 155
  Top Layer w7.87: R154.2@4194.93,459.76 4202.81,451.88 4202.81,430.53 4205.08,428.26 4205.08,310.44 J13.81@4206.16,309.36
NetJ13_82: J13.82 R155.1 | length 323.2
  Top Layer w7.87: v2(4154.97,459.76) R155.1@4155.93,459.76 ; J13.82@4206.16,175.5 4207.2,176.55 4207.2,214.08 v2(4208.25,215.12)
  Bottom Layer w7.87: v2(4154.97,459.76) 4157.29,457.44 4157.29,440.73 4160.07,437.94 4156.14,434.01 4156.14,247.15 4188.16,215.12 v2(4208.25,215.12)
NetJ13_85: J13.85 R158.2 | length 161.2
  Top Layer w7.87: R158.2@4117.05,459.76 4117.05,414.15 4133.32,397.87 4133.32,392.98 4143.17,383.14 J13.85@4143.17,309.36
NetJ13_87: J13.87 R159.2 | length 163
  Top Layer w7.87: R159.2@4081.27,459.76 4083.92,457.1 4083.92,415.78 4101.83,397.87 4101.83,392.98 4111.67,383.14 J13.87@4111.67,309.36
NetJ13_99: J13.99 R160.2 | length 154.7
  Top Layer w7.87: J13.99@3922.69,309.36 3921.85,310.21 3921.85,428.26 3923.55,429.97 3923.55,451.88 R160.2@3931.43,459.76
NetJ13_101: J13.101 R161.2 | length 153.8
  Top Layer w7.87: J13.101@3891.2,309.36 3890.1,310.46 3890.1,455.78 R161.2@3895,460.68
NetJ13_103: J13.103 R162.2 | length 153.6
  Top Layer w7.87: R162.2@3857,461.88 3858.35,460.53 3858.35,310.71 J13.103@3859.7,309.36
NetJ13_105: J13.105 R163.2 | length 156.3
  Top Layer w7.87: R163.2@3816.27,460.68 3824.14,452.8 3824.14,431.64 3826.6,429.18 3826.6,310.97 J13.105@3828.21,309.36
NetQ1_1_4: Q1_1.4 R2_1.1 R8_1.2 | length 50.7
  Top Layer w7.87: R8_1.2@912.24,2935.04 v2(912.24,2979.33)
  Bottom Layer w7.87: R2_1.1@905.87,2979.33 v2(912.24,2979.33)
NetQ1_2_4: Q1_2.4 R2_2.1 R8_2.2 | length 57
  Top Layer w7.87: R8_2.2@2332.36,2938.62 v2(2332.36,2982.91)
  Bottom Layer w7.87: R2_2.1@2325.98,2982.91 v2(2332.36,2982.91) ; R2_2.1@2326.85,2983.44 R2_2.1@2333.23,2983.44
NetQ1_3_4: Q1_3.4 R2_3.1 R8_3.2 | length 50.7
  Top Layer w7.87: R8_3.2@3807.36,2938.62 v2(3807.36,2982.91)
  Bottom Layer w7.87: R2_3.1@3800.98,2982.91 v2(3807.36,2982.91)
NetQ1_4_4: Q1_4.4 R2_4.1 R8_4.2 | length 50.7
  Top Layer w7.87: R8_4.2@5253.14,2931.78 v2(5253.14,2976.07)
  Bottom Layer w7.87: R2_4.1@5246.76,2976.07 v2(5253.14,2976.07)
NetQ4_1_4: Q4_1.4 R7_1.2 R10_1.2 | length 73.1
  Top Layer w7.87: R10_1.2@636.38,2935.04 638.42,2937.09 Q4_1.4@638.42,2983.86
  Top Layer w20: Q4_1.4@638.42,2983.86 646.3,2983.86 646.34,2983.9 646.34,2990.15 650.24,2994.05 v2(650.24,2997.83)
NetQ4_2_4: Q4_2.4 R7_2.2 R10_2.2 | length 73.1
  Top Layer w7.87: R10_2.2@2056.5,2938.62 2058.54,2940.67 Q4_2.4@2058.54,2987.44
  Top Layer w20: Q4_2.4@2058.54,2987.44 2066.42,2987.44 2066.46,2987.48 2066.46,2993.73 2070.35,2997.63 v2(2070.35,3001.42)
NetQ4_3_4: Q4_3.4 R7_3.2 R10_3.2 | length 73.1
  Top Layer w7.87: R10_3.2@3531.5,2938.62 3533.54,2940.67 Q4_3.4@3533.54,2987.44
  Top Layer w20: Q4_3.4@3533.54,2987.44 3541.42,2987.44 3541.46,2987.48 3541.46,2993.73 3545.35,2997.63 v2(3545.35,3001.42)
NetQ4_4_4: Q4_4.4 R7_4.2 R10_4.2 | length 73.1
  Top Layer w7.87: R10_4.2@4977.28,2931.78 4979.32,2933.83 Q4_4.4@4979.32,2980.6
  Top Layer w20: Q4_4.4@4979.32,2980.6 4987.2,2980.6 4987.24,2980.64 4987.24,2986.89 4991.13,2990.79 v2(4991.13,2994.58)
NetQ5_1_1: Q5_1.1 R14_1.1 | length 62.8
  Top Layer w20: Q5_1.1@1515.34,5142.76 R14_1.1@1578.13,5142.76
NetQ5_1_2: Q5_1.2 Q6_1.3 | length 368.1
  Top Layer w7.87: Q5_1.2@1515.34,5192.76 1669.13,5192.76 1781.84,5080.04 1781.84,5034.01 Q6_1.3@1788.09,5027.76
NetQ5_1_3: Q5_1.3 Q7_1.4 R18_1.2 | length 143.7
  Top Layer w20: R18_1.2@1205.97,5192.76 Q5_1.3@1279.12,5192.76 1278.43,5193.44 1278.43,5262.07 Q7_1.4@1277.74,5262.76
NetQ5_2_1: Q5_2.1 R14_2.1 | length 62.8
  Top Layer w20: Q5_2.1@2935.46,5146.34 R14_2.1@2998.25,5146.34
NetQ5_2_2: Q5_2.2 Q6_2.3 | length 363.9
  Top Layer w7.87: Q5_2.2@2935.46,5196.34 3082.2,5196.34 3201.96,5076.58 3201.96,5037.59 Q6_2.3@3208.21,5031.34
NetQ5_2_3: Q5_2.3 Q7_2.4 R18_2.2 | length 143.7
  Top Layer w20: R18_2.2@2626.09,5196.34 Q5_2.3@2699.24,5196.34 2698.55,5197.03 2698.55,5265.65 Q7_2.4@2697.86,5266.34
NetQ5_3_1: Q5_3.1 R14_3.1 | length 62.8
  Top Layer w20: Q5_3.1@4410.46,5146.34 R14_3.1@4473.25,5146.34
NetQ5_3_2: Q5_3.2 Q6_3.3 | length 362.4
  Top Layer w7.87: Q5_3.2@4410.46,5196.34 4554.6,5196.34 4676.96,5073.98 4676.96,5037.59 Q6_3.3@4683.21,5031.34
NetQ5_3_3: Q5_3.3 Q7_3.4 R18_3.2 | length 143.7
  Top Layer w20: R18_3.2@4101.09,5196.34 Q5_3.3@4174.24,5196.34 4173.55,5197.03 4173.55,5265.65 Q7_3.4@4172.86,5266.34
NetQ5_4_1: Q5_4.1 R14_4.1 | length 62.8
  Top Layer w20: Q5_4.1@5856.24,5139.5 R14_4.1@5919.03,5139.5
NetQ5_4_2: Q5_4.2 Q6_4.3 | length 358.6
  Top Layer w7.87: Q5_4.2@5856.24,5189.5 5993.79,5189.5 6122.74,5060.55 6122.74,5030.75 Q6_4.3@6128.99,5024.5
NetQ5_4_3: Q5_4.3 Q7_4.4 R18_4.2 | length 143.7
  Top Layer w20: R18_4.2@5546.87,5189.5 Q5_4.3@5620.02,5189.5 5619.33,5190.19 5619.33,5258.81 Q7_4.4@5618.64,5259.5
NetQ6_1_1: Q6_1.1 Q8_1.1 R15_1.1 R19_1.1 R25_1.1 | length 627.7
  Top Layer w6: R19_1.1@1184.35,5032.76 R19_1.1@1197.28,5045.68
  Top Layer w7.87: Q8_1.1@1119.47,5022.95 1129.28,5032.76 R19_1.1@1184.35,5032.76 ; R19_1.1@1198.26,5045.68 1199.04,5046.46 1211.05,5046.46 1215.85,5051.26 1215.85,5056.35 1222.77,5063.27 1226.99,5063.27 1231.6,5067.88 1231.6,5067.99 1232.66,5069.06 R15_1.1@1233.65,5069.06 ; R15_1.1@1247.35,5082.76 1247.35,5077.65 v2(1250,5075)
  Top Layer w20: v2(1651.13,5055.55) 1658.92,5063.35 1691.8,5063.35 Q6_1.1@1693.61,5065.16
  Bottom Layer w7.87: v2(1250,5075) 1250,5075.72 1282.42,5108.14 1598.53,5108.14 v2(1651.13,5055.55)
NetQ6_2_1: Q6_2.1 Q8_2.1 R15_2.1 R19_2.1 R25_2.1 | length 661.9
  Top Layer w6: R19_2.1@2604.47,5036.34 R19_2.1@2617.4,5049.26
  Top Layer w7.87: Q8_2.1@2539.59,5026.54 R19_2.1@2593.68,5026.54 ; R19_2.1@2604.47,5036.34 2618.91,5050.78 2629.38,5050.78 2635.97,5057.37 2635.97,5059.93 2642.89,5066.85 2647.1,5066.85 2651.72,5071.46 2651.72,5071.57 2666.48,5086.34 R15_2.1@2667.46,5086.34 2670,5088.87 v2(2670,5090)
  Top Layer w20: R19_2.1@2593.68,5026.54 2603.49,5036.34 R19_2.1@2604.47,5036.34 ; v2(3063.45,5051.34) 3079.04,5066.93 3111.91,5066.93 Q6_2.1@3113.72,5068.74
  Bottom Layer w7.87: v2(2670,5090) 2833.11,5090 2854.57,5111.46 3003.33,5111.46 v2(3063.45,5051.34)
NetQ6_3_1: Q6_3.1 Q8_3.1 R15_3.1 R19_3.1 R25_3.1 | length 638.8
  Top Layer w6: R19_3.1@4079.47,5036.34 R19_3.1@4092.4,5049.26
  Top Layer w7.87: Q8_3.1@4014.59,5026.54 R19_3.1@4068.68,5026.54 ; R19_3.1@4092.4,5049.26 4093.38,5049.26 4095.22,5051.1 4095.22,5051.21 4099.83,5055.83 4106.86,5055.83 4117.89,5066.85 4122.1,5066.85 4126.72,5071.46 4126.72,5071.57 4141.48,5086.34 v2(4142.46,5086.34)
  Top Layer w20: R19_3.1@4068.68,5026.54 4078.49,5036.34 R19_3.1@4079.47,5036.34 ; v2(4538.45,5051.34) 4554.04,5066.93 4586.91,5066.93 Q6_3.1@4588.72,5068.74
  Bottom Layer w7.87: v2(4142.46,5086.34) 4164.28,5108.15 4481.64,5108.15 v2(4538.45,5051.34)
NetQ6_4_1: Q6_4.1 Q8_4.1 R15_4.1 R19_4.1 R25_4.1 | length 628.9
  Top Layer w6: R19_4.1@5525.25,5029.5 R19_4.1@5538.18,5042.42
  Top Layer w7.87: Q8_4.1@5460.37,5019.7 R19_4.1@5514.46,5019.7 ; R19_4.1@5538.18,5042.42 5540.02,5044.26 5541,5044.26 5545.72,5048.99 5549.83,5048.99 5565.58,5064.74 5572.5,5064.74 5582.26,5074.5 R15_4.1@5582.26,5079.5 ; v2(5583.34,5081.37) 5585.22,5079.5 R15_4.1@5588.24,5079.5
  Top Layer w20: R19_4.1@5514.46,5019.7 5524.27,5029.5 R19_4.1@5525.25,5029.5 ; v2(5983.24,5044.5) 5984.23,5044.5 5999.82,5060.09 6032.69,5060.09 Q6_4.1@6034.5,5061.9
  Bottom Layer w7.87: v2(5583.34,5081.37) 5946.37,5081.37 v2(5983.24,5044.5)
NetQ7_1_1: Q7_1.1 Q8_1.3 | length 567.1
  Bottom Layer w7.87: v2(1040.73,5060.35) 1043.05,5062.67 1052.67,5062.67 1252.07,5262.07 v2(1524.28,5262.07)
NetQ7_1_2: Q7_1.2 R29_1.1 | length 55.4
  Top Layer w20: Q7_1.2@1513.96,5312.76 R29_1.1@1569.35,5312.76
NetQ7_1_3: Q7_1.3 R27_1.2 R31_1.1 | length 226.2
  Top Layer w10: R27_1.2@1089.47,5237.76 R31_1.1@1135.9,5237.76 ; R31_1.1@1135.28,5237.76 1139.83,5237.76 1147.23,5245.15 1147.23,5255.78 1204.2,5312.76 Q7_1.3@1277.74,5312.76
NetQ7_2_1: Q7_2.1 Q8_2.3 | length 557.1
  Bottom Layer w7.87: v2(2460.85,5063.94) 2575.24,5178.32 2815.86,5178.32 2903.87,5266.34 v2(2934.08,5266.34)
NetQ7_2_2: Q7_2.2 R29_2.1 | length 55.4
  Top Layer w20: Q7_2.2@2934.08,5316.34 R29_2.1@2989.47,5316.34
NetQ7_2_3: Q7_2.3 R27_2.2 R31_2.1 | length 226.2
  Top Layer w10: R27_2.2@2509.59,5241.34 R31_2.1@2556.01,5241.34 ; R31_2.1@2555.4,5241.34 2559.95,5241.34 2567.35,5248.73 2567.35,5259.36 2624.32,5316.34 Q7_2.3@2697.86,5316.34
NetQ7_3_1: Q7_3.1 Q8_3.3 | length 567.1
  Bottom Layer w7.87: v2(3935.85,5063.94) 4137.56,5265.65 v2(4419.39,5265.65)
NetQ7_3_2: Q7_3.2 R29_3.1 | length 55.4
  Top Layer w20: Q7_3.2@4409.08,5316.34 R29_3.1@4464.47,5316.34
NetQ7_3_3: Q7_3.3 R27_3.2 R31_3.1 | length 226.2
  Top Layer w20: R27_3.2@3984.59,5241.34 R31_3.1@4031.01,5241.34 ; R31_3.1@4030.4,5241.34 4034.95,5241.34 4042.35,5248.73 4042.35,5259.36 4099.32,5316.34 Q7_3.3@4172.86,5316.34
NetQ7_4_1: Q7_4.1 Q8_4.3 | length 567.1
  Bottom Layer w7.87: v2(5381.63,5057.1) 5583.34,5258.81 v2(5865.17,5258.81)
NetQ7_4_2: Q7_4.2 R29_4.1 | length 55.4
  Top Layer w20: Q7_4.2@5854.86,5309.5 R29_4.1@5910.25,5309.5
NetQ7_4_3: Q7_4.3 R27_4.2 R31_4.1 | length 226.2
  Top Layer w20: R27_4.2@5430.37,5234.5 R31_4.1@5476.79,5234.5 ; R31_4.1@5476.18,5234.5 5480.73,5234.5 5488.13,5241.9 5488.13,5252.52 5545.1,5309.5 Q7_4.3@5618.64,5309.5
NetR16_1_1: R16_1.1 U2_1.3 | length 167.3
  Top Layer w7.87: R16_1.1@1247.35,4882.76 1248.33,4882.76 1267.82,4902.24 1271.92,4902.24 1290.26,4920.58 1290.26,4977.99 1294.88,4982.6 1334.17,4982.6 U2_1.3@1338.02,4986.46
NetR16_2_1: R16_2.1 U2_2.3 | length 173.2
  Top Layer w7.87: R16_2.1@2667.46,4886.34 2668.45,4886.34 2687.94,4905.83 2705.77,4905.83 2710.38,4910.44 2710.38,4977.95 2717.55,4985.12 2753.22,4985.12 U2_2.3@2758.14,4990.04
NetR16_3_1: R16_3.1 U2_3.3 | length 169.8
  Top Layer w7.87: R16_3.1@4142.46,4886.34 4157.23,4901.1 4166.58,4901.1 4185.38,4919.9 4185.38,4981.57 4189.99,4986.18 4229.28,4986.18 U2_3.3@4233.14,4990.04
NetR16_4_1: R16_4.1 U2_4.3 | length 163.3
  Top Layer w7.87: R16_4.1@5588.24,4879.5 5603.01,4894.26 5608.1,4894.26 5623.92,4910.09 5623.92,4968.34 5639.75,4984.17 5667.12,4984.17 U2_4.3@5672.04,4989.09
NetR17_1_2: R17_1.2 U3_1.3 | length 41.6
  Top Layer w7.87: U3_1.3@818.84,2819.26 820.03,2818.07 856.05,2818.07 R17_1.2@858.8,2815.32
NetR17_2_2: R17_2.2 U3_2.3 | length 41.6
  Top Layer w7.87: U3_2.3@2238.66,2823.82 2245.75,2823.82 2248.9,2820.67 2254.2,2820.67 2254.99,2819.88 R17_2.2@2278.62,2819.88
NetR17_3_2: R17_3.2 U3_3.3 | length 42.6
  Top Layer w7.87: U3_3.3@3713.66,2823.82 3714.45,2823.03 3723.47,2823.03 3724.81,2821.69 3742.88,2821.69 3744.08,2822.9 3750.61,2822.9 R17_3.2@3753.62,2819.88
NetR17_4_2: R17_4.2 U3_4.3 | length 42.6
  Top Layer w7.87: U3_4.3@5159.44,2816.98 5160.23,2816.19 5169.25,2816.19 5170.59,2814.85 5188.66,2814.85 5189.86,2816.06 5196.39,2816.06 R17_4.2@5199.4,2813.04
NetR19_1_2: R19_1.2 U2_1.1 | length 91.1
  Top Layer w7.87: R19_1.2@1251.09,5036.5 U2_1.1@1336.88,5036.5
  Top Layer w20: R19_1.2@1247.35,5032.76 R19_1.2@1251.09,5036.5
NetR19_2_2: R19_2.2 U2_2.1 | length 91.1
  Top Layer w7.87: R19_2.2@2671.2,5040.08 U2_2.1@2757,5040.08
  Top Layer w20: R19_2.2@2667.46,5036.34 R19_2.2@2671.2,5040.08
NetR19_3_2: R19_3.2 U2_3.1 | length 91.1
  Top Layer w7.87: R19_3.2@4146.2,5040.08 U2_3.1@4232,5040.08
  Top Layer w20: R19_3.2@4142.46,5036.34 R19_3.2@4146.2,5040.08
NetR19_4_2: R19_4.2 U2_4.1 | length 93
  Top Layer w7.87: R19_4.2@5588.24,5029.5 5599.01,5040.27 U2_4.1@5676.81,5040.27
NetR20_1_1: R20_1.1 R22_1.2 U2_1.2 | length 152.8
  Top Layer w7.87: R20_1.1@1247.35,4932.76 R22_1.2@1247.35,4982.76 1261.05,4996.46 1278.89,4996.46 1294.48,5012.05 U2_1.2@1338.02,5012.05
NetR20_2_1: R20_2.1 R22_2.2 U2_2.2 | length 152.8
  Top Layer w7.87: R20_2.1@2667.46,4936.34 R22_2.2@2667.46,4986.34 2681.17,5000.04 2699.01,5000.04 2714.6,5015.63 U2_2.2@2758.14,5015.63
NetR20_3_1: R20_3.1 R22_3.2 U2_3.2 | length 152.8
  Top Layer w7.87: R20_3.1@4142.46,4936.34 R22_3.2@4142.46,4986.34 4156.17,5000.04 4174.01,5000.04 4189.6,5015.63 U2_3.2@4233.14,5015.63
NetR20_4_1: R20_4.1 R22_4.2 U2_4.2 | length 157.9
  Top Layer w7.87: R20_4.1@5588.24,4929.5 5576.73,4941.02 5576.73,4967.99 5602.92,4994.17 5612.91,4994.17 5633.41,5014.68 U2_4.2@5672.04,5014.68
NetR25_1_2: R25_1.2 U2_1.7 | length 311.7
  Top Layer w7.87: U2_1.7@1511.25,5012.05 1491.57,5012.05 1486.65,5016.97 1482.03,5016.97 1478.96,5016.97 1443.16,5052.77 1443.16,5102.6 1450.08,5109.52 1538.6,5109.52 1574.46,5073.66 1574.46,5052.65 R25_1.2@1579.35,5047.76
NetR25_2_2: R25_2.2 U2_2.7 | length 312.2
  Top Layer w7.87: U2_2.7@2931.37,5015.63 2911.69,5015.63 2906.76,5020.55 2902.15,5020.55 2899.08,5020.55 2869.06,5050.56 2869.06,5106.03 2876.3,5113.27 2965.03,5113.27 2971.95,5106.35 2971.95,5070.72 2976.56,5066.1 2984.71,5066.1 R25_2.2@2999.47,5051.34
